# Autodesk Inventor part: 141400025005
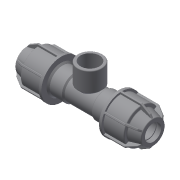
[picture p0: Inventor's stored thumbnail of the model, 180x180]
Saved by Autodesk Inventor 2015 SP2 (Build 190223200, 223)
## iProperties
Created: 2017-08
Part Number: 141400025005
Material: Generic
Description: PLASSON L.14 TEE FEMALE ADAPTOR (SILVER) 25 x 1/2" x 25
Document SubType Name: Modeling
Designer: KIM
Density: 1 g/cm^3
Appearance: Default
Author: KIM
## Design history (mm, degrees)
derived "141400.ipt"
feature "Solid1::141400.ipt"
feature "Solid2::141400.ipt"
tag "TaggingFeature1"
body "Solid1"
other parameters: "d1" = 25, "d2" = 48, "d4" = 15 deg, "d5" = 31.68, "d6" = 10.4544, "d16" = 25.5, "d17" = 2.4, "d24" = 2.4, "d25" = 45, "d26" = 37.5, "d27" = 2.4, "d28" = 135 deg, "d29" = 1.44, "d31" = 1.25, "d46" = 150 deg, "d49" = 2.5, "d50" = 0, "d58" = 0.75, "d61" = 360 deg, "d63" = 22.5, "d64" = 61.5, "d80" = 36, "d81" = 2, "d84" = 2.4, "d94" = 45, "d95" = 18.631, "d96" = 24.2203, "d97" = 18, "d98" = 12.5, "d99" = 16.95421, "d100" = 135 deg, "d108" = 1.25, "d111" = 0, "d_" = 25, "G_" = 18.631, "H_" = 123, "l_" = 48, "l_2" = 18, "A_" = 45
